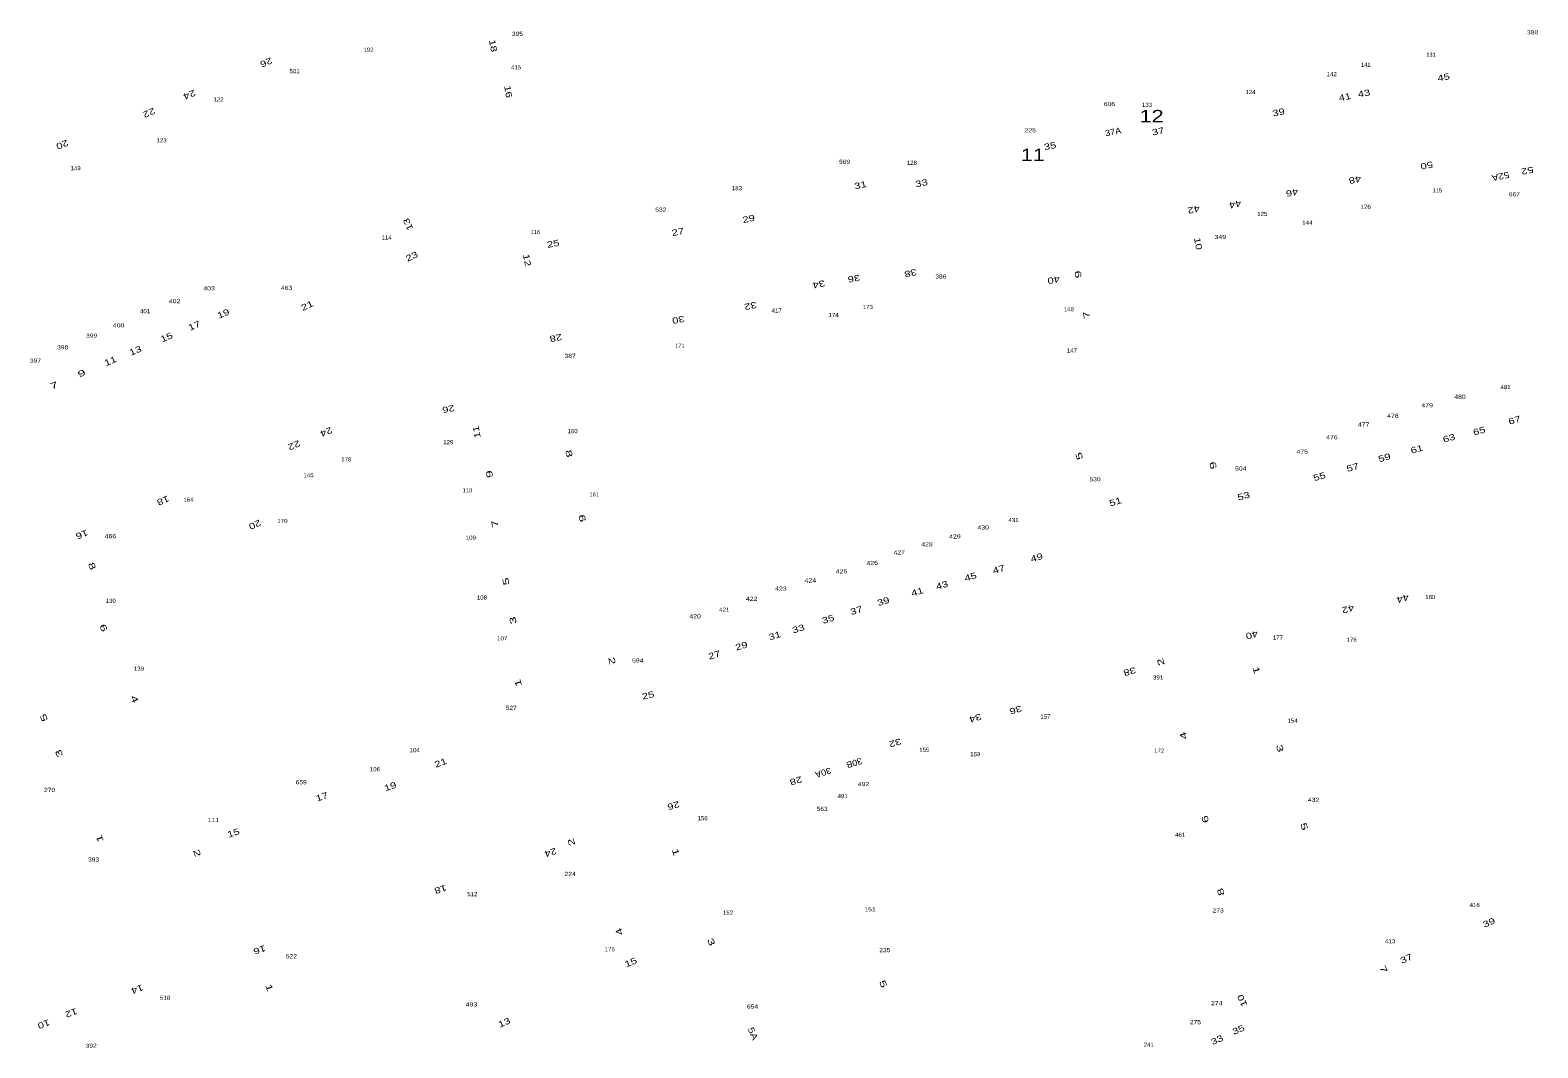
# Model space of a CAD drawing. Extents: x -828673 to -815583, y -1077737 to -1063807.
# Drawn here: x -820516.3 to -820152.3, y -1073845.3 to -1073599.5 of the extents above; entities that cross this region are included whole.
import ezdxf
from ezdxf.enums import TextEntityAlignment as Align

# ---------------------------------------------------------------- set-up
doc = ezdxf.new("R2010")
doc.units = 0
doc.header["$LTSCALE"] = 0.4
doc.layers.add('1', color=7, linetype='Continuous')
doc.layers.add('2', color=7, linetype='Continuous')

msp = doc.modelspace()

# ---------------------------------------------------------------- texts
at = {"layer": '1'}
for s, width, p in [('395', 1.2, (-820398.671, -1073600.927)), ('388', 1.2, (-820153.535, -1073600.561)), ('192', 1.1, (-820434.631, -1073604.772)), ('501', 1.1, (-820452.462, -1073609.947)), ('415', 1.1, (-820398.975, -1073609.025)), ('142', 1.1, (-820202.037, -1073610.668)), ('124', 1.1, (-820221.633, -1073614.991)), ('122', 1.1, (-820470.841, -1073616.766)), ('606', 1.2, (-820255.713, -1073617.897)), ('133', 1.1, (-820246.645, -1073618.08)), ('123', 1.1, (-820484.578, -1073626.657)), ('225', 1.2, (-820274.822, -1073624.23)), ('149', 1.1, (-820505.368, -1073633.376)), ('569', 1.2, (-820319.673, -1073631.84)), ('128', 1.1, (-820303.424, -1073632.084)), ('183', 1.1, (-820345.676, -1073638.209)), ('667', 1.2, (-820157.938, -1073639.683)), ('532', 1.2, (-820364.055, -1073643.384)), ('125', 1.1, (-820218.799, -1073644.426)), ('126', 1.1, (-820193.822, -1073642.694)), ('144', 1.15, (-820207.919, -1073646.529)), ('349', 1.25, (-820228.939, -1073649.993)), ('386', 1.2, (-820296.414, -1073659.544)), ('403', 1.25, (-820473.122, -1073662.374)), ('463', 1.25, (-820454.411, -1073662.278)), ('402', 1.25, (-820481.46, -1073665.479)), ('173', 1.1, (-820314.06, -1073666.882)), ('401', 1.1, (-820488.58, -1073667.914)), ('417', 1.1, (-820336.064, -1073667.754)), ('174', 1.1, (-820322.339, -1073668.844)), ('148', 1.1, (-820265.518, -1073667.447)), ('399', 1.2, (-820501.482, -1073673.82)), ('400', 1.25, (-820494.97, -1073671.324)), ('398', 1.2, (-820508.48, -1073676.621)), ('147', 1.1, (-820264.792, -1073677.401)), ('397', 1.2, (-820515.053, -1073679.848)), ('387', 1.2, (-820385.939, -1073678.704)), ('480', 1.25, (-820171.07, -1073688.59)), ('481', 1.1, (-820160.065, -1073686.24)), ('479', 1.25, (-820178.992, -1073690.634)), ('477', 1.25, (-820194.317, -1073695.271)), ('478', 1.25, (-820187.269, -1073693.168)), ('129', 1.1, (-820415.352, -1073699.546)), ('160', 1.1, (-820385.358, -1073696.868)), ('476', 1.25, (-820201.983, -1073698.363)), ('475', 1.25, (-820209.155, -1073701.827)), ('178', 1.1, (-820439.971, -1073703.674)), ('504', 1.25, (-820223.993, -1073705.91)), ('146', 1.1, (-820449.117, -1073707.527)), ('530', 1.2, (-820259.2, -1073708.498)), ('164', 1.1, (-820478.105, -1073713.425)), ('170', 1.1, (-820455.412, -1073718.585)), ('466', 1.25, (-820496.948, -1073722.231)), ('109', 1.1, (-820409.919, -1073722.595)), ('130', 1.1, (-820496.879, -1073737.849)), ('108', 1.1, (-820407.237, -1073737.043)), ('180', 1.1, (-820178.251, -1073736.93)), ('107', 1.1, (-820402.358, -1073746.914)), ('177', 1.1, (-820215.047, -1073746.709)), ('176', 1.1, (-820197.224, -1073747.227)), ('139', 1.1, (-820490.071, -1073754.224)), ('594', 1.25, (-820369.604, -1073752.242)), ('391', 1.1, (-820243.956, -1073756.35)), ('527', 1.2, (-820400.157, -1073763.702)), ('157', 1.1, (-820271.159, -1073765.778)), ('154', 1.1, (-820211.482, -1073766.786)), ('104', 1.1, (-820423.447, -1073773.91)), ('155', 1.1, (-820300.411, -1073773.813)), ('169', 1.1, (-820288.12, -1073774.879)), ('172', 1.1, (-820243.71, -1073774.059)), ('106', 1.1, (-820433.075, -1073778.52)), ('270', 1.2, (-820511.627, -1073783.509)), ('659', 1.2, (-820450.87, -1073781.66)), ('492', 1.25, (-820315.079, -1073782.105)), ('491', 1.1, (-820320.126, -1073785.006)), ('432', 1.25, (-820206.429, -1073785.89)), ('111', 1.2, (-820472.079, -1073790.767)), ('156', 1.1, (-820353.97, -1073790.345)), ('563', 1.2, (-820325.102, -1073788.086)), ('461', 1.1, (-820238.645, -1073794.339)), ('393', 1.2, (-820501.025, -1073800.337)), ('224', 1.25, (-820385.94, -1073803.796)), ('512', 1.1, (-820409.562, -1073808.673)), ('151', 1.2, (-820313.51, -1073812.36)), ('273', 1.2, (-820229.468, -1073812.621)), ('416', 1.1, (-820167.506, -1073811.317)), ('152', 1.1, (-820347.825, -1073813.137)), ('413', 1.1, (-820187.916, -1073820.061)), ('522', 1.2, (-820453.242, -1073823.679)), ('175', 1.1, (-820376.379, -1073821.991)), ('235', 1.2, (-820309.97, -1073822.211)), ('518', 1.1, (-820483.732, -1073833.689)), ('493', 1.25, (-820409.749, -1073835.309)), ('654', 1.2, (-820341.9, -1073835.82)), ('274', 1.25, (-820229.796, -1073835.003)), ('275', 1.2, (-820234.958, -1073839.594)), ('392', 1.2, (-820501.582, -1073845.287)), ('241', 1.1, (-820246.233, -1073845.027))]:
    msp.add_text(s, height=1, dxfattribs=dict(at, width=width)).set_placement(p, align=Align.CENTER)
for s, p in [('141', (-820193.822, -1073608.415)), ('131', (-820178.06, -1073605.979)), ('115', (-820176.511, -1073638.735)), ('116', (-820394.362, -1073648.803)), ('114', (-820430.251, -1073650.101)), ('171', (-820359.448, -1073676.255)), ('110', (-820410.744, -1073711.174)), ('161', (-820380.129, -1073712.126))]:
    msp.add_text(s, height=1, dxfattribs=at).set_placement(p, align=Align.CENTER)
for s, rotation, width, p in [('430', 1.061, 1.25, (-820286.1878, -1073720.1454)), ('431', 0.748, 1.1, (-820278.854, -1073718.3286)), ('428', 0.117, 1.25, (-820299.768, -1073724.2132)), ('429', 1.93, 1.25, (-820293.0158, -1073722.3245)), ('426', 2.33, 1.25, (-820312.9848, -1073728.7188)), ('427', 2.297, 1.25, (-820306.45, -1073726.1756)), ('425', 1.559, 1.25, (-820320.3936, -1073730.7524)), ('423', 359.072, 1.25, (-820335.0621, -1073734.8944)), ('424', 0.721, 1.25, (-820327.9448, -1073732.932)), ('421', 0.783, 1.1, (-820348.7148, -1073739.9808)), ('422', 359.258, 1.25, (-820342.106, -1073737.3649)), ('420', 0.278, 1.25, (-820355.7589, -1073741.5793))]:
    msp.add_text(s, height=1, rotation=rotation, dxfattribs=dict(at, width=width)).set_placement(p, align=Align.CENTER)
at = {"layer": '2'}
for s, rotation, width, p in [('18', 281.021, 1.35, (-820405.2654, -1073603.4476)), ('26', 202.512, 1.35, (-820459.5998, -1073606.6465)), ('45', 10.944, 1.35, (-820174.8774, -1073611.6524)), ('24', 202.901, 1.35, (-820478.1616, -1073614.4413)), ('16', 280.947, 1.35, (-820401.6153, -1073614.5276)), ('41', 11.253, 1.35, (-820198.7284, -1073616.4114)), ('43', 10.392, 1.35, (-820194.1083, -1073615.5516)), ('22', 203.736, 1.35, (-820487.9191, -1073618.8171)), ('39', 11.845, 1.35, (-820214.7159, -1073620.1062)), ('20', 202.908, 1.35, (-820508.8546, -1073626.4845)), ('37A', 11.333, 1.1, (-820254.6799, -1073624.8364)), ('37', 11.614, 1.35, (-820243.8065, -1073624.717)), ('35', 11.133, 1.35, (-820269.9148, -1073628.2515)), ('50', 191.31, 1.35, (-820179.2454, -1073631.4881)), ('52', 191.138, 1.35, (-820154.9321, -1073632.7366)), ('31', 12.052, 1.35, (-820315.6726, -1073637.6918)), ('33', 11.583, 1.35, (-820300.9516, -1073637.1998)), ('48', 191.2, 1.35, (-820196.5568, -1073634.9522)), ('52A', 192.131, 1.2, (-820161.4289, -1073634.1347)), ('46', 191.611, 1.35, (-820211.7655, -1073638.0469)), ('29', 11.871, 1.35, (-820342.6758, -1073645.8244)), ('42', 192.171, 1.35, (-820235.5064, -1073642.1314)), ('44', 191.561, 1.35, (-820225.4907, -1073640.8916)), ('13', 114.722, 1.35, (-820424.3915, -1073646.1382)), ('27', 11.338, 1.35, (-820359.7774, -1073648.9942)), ('25', 10.548, 1.35, (-820389.9018, -1073651.8596)), ('10', 282.075, 1.35, (-820235.0121, -1073651.2446)), ('23', 25.222, 1.35, (-820423.8446, -1073654.85)), ('12', 280.58, 1.35, (-820397.0657, -1073655.2193)), ('36', 190.347, 1.35, (-820317.5398, -1073658.7972)), ('38', 191.339, 1.35, (-820303.8875, -1073657.4939)), ('9', 101.389, 1.65, (-820262.553, -1073658.3786)), ('34', 191.493, 1.35, (-820326.0366, -1073660.1828)), ('40', 191.378, 1.35, (-820269.3375, -1073659.1439)), ('21', 25.327, 1.35, (-820449.1148, -1073666.7335)), ('32', 191.524, 1.35, (-820342.5227, -1073665.4146)), ('17', 22.952, 1.35, (-820476.3995, -1073671.6013)), ('19', 22.948, 1.35, (-820469.4014, -1073668.6784)), ('30', 191.261, 1.35, (-820359.9505, -1073668.7548)), ('7', 101.045, 1.65, (-820260.5165, -1073668.1867)), ('15', 22.921, 1.35, (-820483.0946, -1073674.4032)), ('28', 191.411, 1.35, (-820389.5421, -1073673.1627)), ('13', 22.952, 1.35, (-820490.6405, -1073677.6293)), ('11', 22.921, 1.35, (-820496.6746, -1073680.1492)), ('7', 22.921, 1.65, (-820510.2576, -1073686.0051)), ('9', 22.952, 1.65, (-820503.6245, -1073683.0819)), ('26', 191.653, 1.35, (-820415.476, -1073690.3119)), ('24', 203.115, 1.35, (-820445.1146, -1073695.8736)), ('11', 100.934, 1.35, (-820407.7974, -1073696.4473)), ('65', 15.832, 1.35, (-820166.2146, -1073697.0474)), ('67', 15.9, 1.35, (-820157.6825, -1073694.4478)), ('22', 202.944, 1.35, (-820452.8856, -1073699.1075)), ('63', 16.174, 1.35, (-820173.5109, -1073698.7768)), ('8', 281.117, 1.65, (-820386.9454, -1073701.9409)), ('5', 106.755, 1.65, (-820262.304, -1073702.1887)), ('59', 15.968, 1.35, (-820189.1078, -1073703.484)), ('61', 15.63, 1.35, (-820181.3031, -1073701.4328)), ('9', 100.893, 1.65, (-820404.7061, -1073706.6252)), ('6', 285.803, 1.65, (-820231.4172, -1073704.8463)), ('57', 16.174, 1.35, (-820196.7749, -1073705.8338)), ('55', 15.767, 1.35, (-820204.8118, -1073708.0612)), ('18', 202.834, 1.35, (-820484.5155, -1073712.4637)), ('51', 16.87, 1.35, (-820254.0472, -1073714.153)), ('53', 15.987, 1.35, (-820223.1116, -1073712.7615)), ('6', 281.653, 1.65, (-820383.7458, -1073717.562)), ('16', 202.024, 1.35, (-820504.1162, -1073720.6424)), ('20', 204.024, 1.35, (-820462.3437, -1073718.2883)), ('7', 101.233, 1.65, (-820403.4005, -1073718.5961)), ('8', 292.468, 1.65, (-820502.0725, -1073729.2499)), ('49', 16.887, 1.35, (-820273.0724, -1073727.6216)), ('45', 16.785, 1.35, (-820289.0486, -1073732.2721)), ('47', 16.812, 1.35, (-820282.2224, -1073730.4553)), ('5', 100.776, 1.65, (-820400.7192, -1073732.5242)), ('41', 16.768, 1.35, (-820301.9264, -1073735.8845)), ('43', 16.825, 1.35, (-820295.9486, -1073734.307)), ('37', 16.809, 1.35, (-820316.5974, -1073740.3834)), ('39', 16.754, 1.35, (-820310.1022, -1073738.2089)), ('42', 195.55, 1.35, (-820198.2919, -1073738.6134)), ('44', 195.882, 1.35, (-820185.0678, -1073736.0838)), ('3', 101.41, 1.65, (-820399.0054, -1073741.9504)), ('35', 16.861, 1.35, (-820323.425, -1073742.4892)), ('6', 293.725, 1.65, (-820499.3105, -1073744.1792)), ('31', 16.847, 1.35, (-820336.3264, -1073746.4847)), ('33', 16.723, 1.35, (-820330.6143, -1073744.8147)), ('40', 196.256, 1.35, (-820221.5185, -1073744.8873)), ('27', 16.917, 1.35, (-820350.8982, -1073751.1427)), ('29', 16.756, 1.35, (-820344.3622, -1073748.9638)), ('2', 282.94, 1.65, (-820376.5531, -1073752.0095)), ('38', 196.367, 1.35, (-820251.0432, -1073753.7283)), ('2', 106.358, 1.65, (-820242.6046, -1073751.9117)), ('1', 286.682, 1.65, (-820220.9412, -1073754.2762)), ('1', 105.767, 1.65, (-820397.8012, -1073756.9808)), ('4', 293.501, 1.65, (-820491.8032, -1073761.3879)), ('25', 13.43, 1.35, (-820366.9487, -1073760.8953)), ('36', 196.743, 1.35, (-820278.5734, -1073762.9947)), ('5', 113.215, 1.65, (-820512.3285, -1073765.2881)), ('34', 197.215, 1.35, (-820288.325, -1073764.9649)), ('32', 196.719, 1.35, (-820307.6617, -1073770.9472)), ('4', 107.361, 1.65, (-820237.1227, -1073769.7018)), ('3', 112.868, 1.65, (-820508.6601, -1073773.9305)), ('30B', 196.928, 1.1, (-820317.5491, -1073775.8015)), ('3', 287.233, 1.65, (-820215.2615, -1073773.1883)), ('21', 20.007, 1.35, (-820416.9626, -1073777.1673)), ('30A', 196.928, 1.1, (-820325.0661, -1073778.1295)), ('19', 19.667, 1.35, (-820429.1339, -1073782.8818)), ('28', 196.907, 1.35, (-820331.6289, -1073780.108)), ('17', 19.109, 1.35, (-820445.649, -1073785.384)), ('26', 196.404, 1.35, (-820361.1977, -1073786.0771)), ('6', 105.596, 1.65, (-820231.8815, -1073789.9001)), ('15', 17.958, 1.35, (-820467.0232, -1073794.1133)), ('5', 287.103, 1.65, (-820209.4045, -1073792.0629)), ('1', 109.459, 1.65, (-820498.837, -1073794.5079)), ('24', 198.476, 1.35, (-820390.8908, -1073797.4121)), ('2', 107.43, 1.65, (-820384.9467, -1073795.4032)), ('2', 289.322, 1.65, (-820476.7342, -1073798.4778)), ('1', 286.577, 1.65, (-820361.1469, -1073798.2235)), ('18', 198.398, 1.35, (-820417.4708, -1073806.3069)), ('8', 106.625, 1.65, (-820228.1189, -1073807.4446)), ('39', 23.608, 1.35, (-820163.7739, -1073815.7372)), ('4', 114.002, 1.65, (-820373.3747, -1073816.9826)), ('3', 293.215, 1.65, (-820352.5635, -1073820.0269)), ('16', 198.094, 1.35, (-820461.1521, -1073820.9363)), ('37', 24.28, 1.35, (-820183.7249, -1073824.4214)), ('15', 22.997, 1.35, (-820371.0095, -1073825.3444)), ('7', 293.496, 1.65, (-820190.2103, -1073826.628)), ('14', 200.117, 1.35, (-820490.7095, -1073830.4425)), ('1', 288.783, 1.65, (-820459.2987, -1073830.997)), ('5', 292.759, 1.65, (-820311.0248, -1073830.1679)), ('10', 113.568, 1.35, (-820222.9639, -1073833.6074)), ('12', 200.206, 1.35, (-820506.6539, -1073836.1598)), ('10', 200.746, 1.35, (-820513.2918, -1073838.8874)), ('13', 23.319, 1.35, (-820401.5689, -1073839.8782)), ('5A', 292.95, 1.3, (-820342.4709, -1073842.1676)), ('35', 23.809, 1.35, (-820224.2693, -1073841.601)), ('33', 23.775, 1.35, (-820229.4314, -1073844.061))]:
    msp.add_text(s, height=1.5, rotation=rotation, dxfattribs=dict(at, width=width)).set_placement(p, align=Align.CENTER)
at = {"layer": '2', "width": 1.3}
for s, p in [('12', (-820245.529, -1073621.8)), ('11', (-820274.219, -1073631.16))]:
    msp.add_text(s, height=3, dxfattribs=at).set_placement(p, align=Align.CENTER)

doc.saveas('drawing.dxf')
